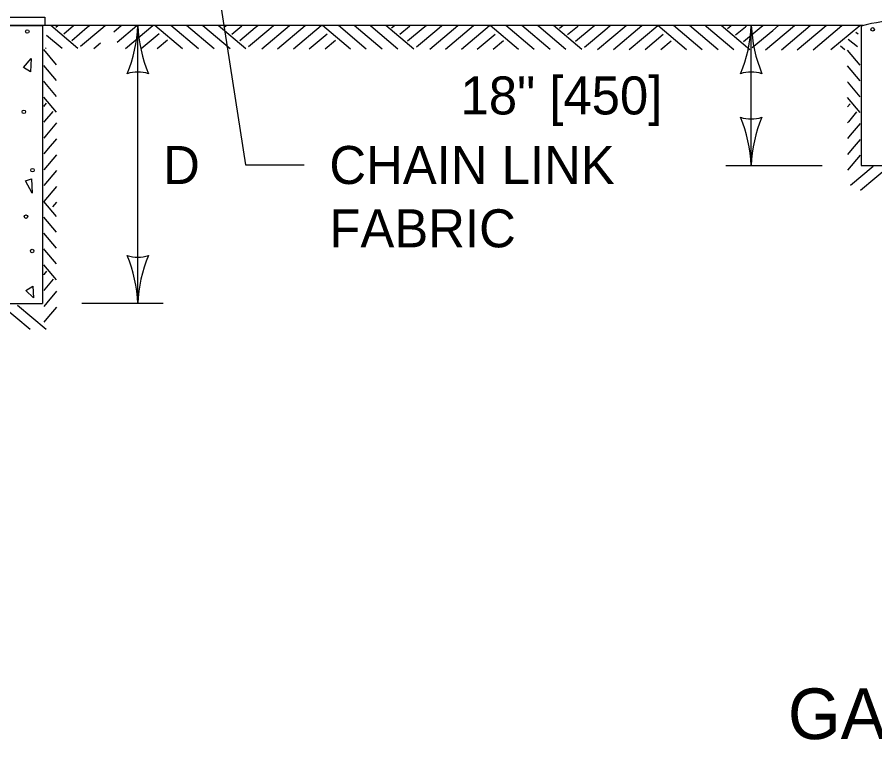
# Model space of a CAD drawing. Extents: x 49973.1 to 50021, y 49987.6 to 50015.4.
# Drawn here: x 50004.493 to 50005.847, y 49993.862 to 49995.003 of the extents above; entities that cross this region are included whole.
import ezdxf

# ---------------------------------------------------------------- set-up
doc = ezdxf.new("R2010")
doc.units = 0
for name, color, linetype in [('Level 1', 7, 'Continuous'), ('Level 2', 7, 'Continuous'), ('Level 3', 7, 'Continuous')]:
    doc.layers.add(name, color=color, linetype=linetype)

msp = doc.modelspace()

# ---------------------------------------------------------------- linework, layer by layer
at = {"layer": 'Level 1'}
for p, q in [((50004.4035, 49994.9902), (50004.5335, 49994.9902)), ((50004.5335, 49994.9902), (50004.5335, 49994.5511)), ((50005.8287, 49994.9902), (50004.5335, 49994.9902)), ((50004.5894, 49994.954), (50004.5465, 49994.9901)), ((50004.5544, 49994.9875), (50004.5575, 49994.9901)), ((50004.5671, 49994.9773), (50004.5825, 49994.9901)), ((50004.5796, 49994.9668), (50004.6042, 49994.9874)), ((50004.5935, 49994.9574), (50004.6258, 49994.9845)), ((50004.6042, 49994.9874), (50004.6075, 49994.9901)), ((50004.6258, 49994.9845), (50004.6326, 49994.9901)), ((50004.6459, 49994.9803), (50004.6576, 49994.9901)), ((50004.6515, 49994.9641), (50004.6826, 49994.9901)), ((50004.6644, 49994.954), (50004.7075, 49994.9901)), ((50004.6644, 49994.954), (50004.7075, 49994.9901)), ((50004.6894, 49994.954), (50004.7178, 49994.9778)), ((50004.7545, 49994.9535), (50004.711, 49994.9901)), ((50004.7795, 49994.9535), (50004.736, 49994.9901)), ((50004.8045, 49994.9535), (50004.761, 49994.9901)), ((50004.8295, 49994.9535), (50004.7865, 49994.9896)), ((50004.8545, 49994.9535), (50004.811, 49994.9901)), ((50004.8195, 49994.987), (50004.8232, 49994.9901)), ((50004.8322, 49994.9768), (50004.8479, 49994.9899)), ((50004.8447, 49994.9663), (50004.8693, 49994.9869)), ((50004.8586, 49994.9569), (50004.8909, 49994.984)), ((50004.8693, 49994.9869), (50004.8732, 49994.9901)), ((50004.8795, 49994.9535), (50004.9233, 49994.9901)), ((50004.8909, 49994.984), (50004.8983, 49994.9901)), ((50004.9045, 49994.9535), (50004.9483, 49994.9901)), ((50004.9295, 49994.9535), (50004.9732, 49994.9901)), ((50004.9545, 49994.9535), (50004.9829, 49994.9773)), ((50005.0196, 49994.953), (50004.9755, 49994.9901)), ((50005.0446, 49994.953), (50005.0005, 49994.9901)), ((50005.0696, 49994.953), (50005.0255, 49994.9901)), ((50005.0516, 49994.9891), (50005.0505, 49994.9901)), ((50005.0946, 49994.953), (50005.0516, 49994.9891)), ((50005.1196, 49994.953), (50005.0755, 49994.9901)), ((50005.0846, 49994.9865), (50005.0889, 49994.9901)), ((50005.0973, 49994.9763), (50005.113, 49994.9894)), ((50005.1098, 49994.9658), (50005.1344, 49994.9864)), ((50005.113, 49994.9894), (50005.1139, 49994.9901)), ((50005.1237, 49994.9564), (50005.156, 49994.9835)), ((50005.1344, 49994.9864), (50005.1389, 49994.9901)), ((50005.1446, 49994.953), (50005.189, 49994.9901)), ((50005.156, 49994.9835), (50005.164, 49994.9901)), ((50005.1696, 49994.953), (50005.214, 49994.9901)), ((50005.1946, 49994.953), (50005.2389, 49994.9901)), ((50005.2196, 49994.953), (50005.248, 49994.9768)), ((50005.2847, 49994.9525), (50005.24, 49994.9901)), ((50005.3097, 49994.9525), (50005.265, 49994.9901)), ((50005.3347, 49994.9525), (50005.29, 49994.9901)), ((50005.3167, 49994.9886), (50005.315, 49994.9901)), ((50005.3597, 49994.9525), (50005.3167, 49994.9886)), ((50005.3847, 49994.9525), (50005.34, 49994.9901)), ((50005.3497, 49994.986), (50005.3547, 49994.9902)), ((50005.3624, 49994.9758), (50005.3781, 49994.9889)), ((50005.3749, 49994.9653), (50005.3995, 49994.9859)), ((50005.3781, 49994.9889), (50005.3796, 49994.9901)), ((50005.3888, 49994.9559), (50005.4211, 49994.983)), ((50005.3995, 49994.9859), (50005.4046, 49994.9901)), ((50005.4097, 49994.9525), (50005.4547, 49994.9901)), ((50005.4211, 49994.983), (50005.4297, 49994.9901)), ((50005.4347, 49994.9525), (50005.4797, 49994.9901)), ((50005.4597, 49994.9525), (50005.5045, 49994.9901)), ((50005.5498, 49994.952), (50005.5045, 49994.9901)), ((50005.5748, 49994.952), (50005.5295, 49994.9901)), ((50005.5998, 49994.952), (50005.5545, 49994.9901)), ((50005.5818, 49994.9881), (50005.5795, 49994.9901)), ((50005.6248, 49994.952), (50005.5818, 49994.9881)), ((50005.6498, 49994.952), (50005.6045, 49994.9901)), ((50005.6148, 49994.9855), (50005.6198, 49994.9897)), ((50005.6198, 49994.9897), (50005.6203, 49994.9901)), ((50005.6275, 49994.9753), (50005.6432, 49994.9884)), ((50005.64, 49994.9648), (50005.6646, 49994.9854)), ((50005.6432, 49994.9884), (50005.6453, 49994.9901)), ((50005.6539, 49994.9554), (50005.6862, 49994.9825)), ((50005.6646, 49994.9854), (50005.6703, 49994.9901)), ((50005.6748, 49994.952), (50005.7203, 49994.9901)), ((50005.6862, 49994.9825), (50005.6954, 49994.9901)), ((50005.6998, 49994.952), (50005.7453, 49994.9901)), ((50005.7248, 49994.952), (50005.7702, 49994.9901)), ((50005.7498, 49994.952), (50005.7953, 49994.9901)), ((50005.778, 49994.9521), (50005.8235, 49994.9902)), ((50005.8209, 49994.9763), (50005.8174, 49994.9792)), ((50005.8257, 49994.9894), (50005.8257, 49994.7693)), ((50004.5644, 49994.954), (50004.5398, 49994.9746)), ((50004.7144, 49994.954), (50004.7307, 49994.9677)), ((50004.9795, 49994.9535), (50004.9958, 49994.9672)), ((50005.2446, 49994.953), (50005.2609, 49994.9667)), ((50005.4847, 49994.9525), (50005.5131, 49994.9763)), ((50005.5097, 49994.9525), (50005.526, 49994.9662)), ((50005.8197, 49994.9563), (50005.8053, 49994.9683)), ((50004.5553, 49994.9284), (50004.5354, 49994.9521)), ((50004.5394, 49994.954), (50004.5381, 49994.9551)), ((50004.6144, 49994.954), (50004.6248, 49994.9627)), ((50005.7998, 49994.952), (50005.793, 49994.9577)), ((50005.8242, 49994.9277), (50005.8043, 49994.9514)), ((50004.5553, 49994.9034), (50004.5354, 49994.9271)), ((50005.8242, 49994.9027), (50005.8043, 49994.9264)), ((50004.5369, 49994.9004), (50004.5354, 49994.9021)), ((50004.5553, 49994.8784), (50004.5369, 49994.9004)), ((50005.8058, 49994.8997), (50005.8043, 49994.9014)), ((50005.8242, 49994.8777), (50005.8058, 49994.8997)), ((50004.5553, 49994.8534), (50004.5354, 49994.8771)), ((50005.8242, 49994.8527), (50005.8043, 49994.8764)), ((50004.5395, 49994.8674), (50004.5353, 49994.8624)), ((50005.8084, 49994.8667), (50005.8042, 49994.8617)), ((50004.5497, 49994.8547), (50004.5366, 49994.839)), ((50005.8186, 49994.854), (50005.8055, 49994.8383)), ((50004.5366, 49994.839), (50004.5354, 49994.8375)), ((50004.5553, 49994.8363), (50004.5396, 49994.8176)), ((50005.8055, 49994.8383), (50005.8043, 49994.8368)), ((50005.8242, 49994.8356), (50005.8085, 49994.8169)), ((50004.5396, 49994.8176), (50004.5354, 49994.8125)), ((50005.8085, 49994.8169), (50005.8043, 49994.8118)), ((50004.5553, 49994.8112), (50004.5425, 49994.796)), ((50005.8242, 49994.8105), (50005.8114, 49994.7953)), ((50004.5425, 49994.796), (50004.5354, 49994.7874)), ((50005.8114, 49994.7953), (50005.8043, 49994.7867)), ((50004.5553, 49994.7862), (50004.5354, 49994.7624)), ((50005.8242, 49994.7855), (50005.8043, 49994.7617)), ((50004.5553, 49994.7612), (50004.5354, 49994.7374)), ((50005.8089, 49994.7384), (50005.8445, 49994.7681)), ((50005.8248, 49994.7305), (50005.8698, 49994.7681)), ((50005.8257, 49994.7693), (50005.9557, 49994.7693)), ((50004.5553, 49994.7363), (50004.5354, 49994.7126)), ((50004.5553, 49994.6889), (50004.5354, 49994.7126)), ((50004.5553, 49994.7112), (50004.5492, 49994.704)), ((50004.5553, 49994.6639), (50004.5354, 49994.6876)), ((50004.5553, 49994.6389), (50004.5354, 49994.6626)), ((50004.5374, 49994.6353), (50004.5354, 49994.6376)), ((50004.5553, 49994.6139), (50004.5374, 49994.6353)), ((50004.5553, 49994.5889), (50004.5354, 49994.6126)), ((50004.54, 49994.6023), (50004.5358, 49994.5973)), ((50004.5358, 49994.5973), (50004.5354, 49994.5968)), ((50004.5502, 49994.5896), (50004.5371, 49994.5739)), ((50004.5371, 49994.5739), (50004.5354, 49994.5718)), ((50004.5553, 49994.5706), (50004.5401, 49994.5525)), ((50004.4035, 49994.5511), (50004.5335, 49994.5511)), ((50004.5142, 49994.5101), (50004.4689, 49994.5482)), ((50004.5392, 49994.5101), (50004.4939, 49994.5482)), ((50004.5401, 49994.5525), (50004.5354, 49994.5468)), ((50004.5553, 49994.5455), (50004.543, 49994.5309)), ((50004.543, 49994.5309), (50004.5354, 49994.5217))]:
    msp.add_line(p, q, dxfattribs=at)
for points in [[(50004.4319, 49994.9902), (50004.4319, 49995.0033), (50004.5374, 49995.0033), (50004.5374, 49994.9902)], [(50004.5033, 49994.9239), (50004.5157, 49994.9383), (50004.5143, 49994.9171)], [(50004.5067, 49994.7448), (50004.5163, 49994.7483), (50004.517, 49994.7256)], [(50004.5074, 49994.5719), (50004.5184, 49994.5788), (50004.5191, 49994.5603)]]:
    msp.add_lwpolyline(points, close=True, dxfattribs=at)
for centre in [(50004.5095, 49994.9808), (50005.8439, 49994.9841), (50004.504, 49994.8539), (50004.5177, 49994.7619), (50004.5075, 49994.6885), (50004.5171, 49994.6343)]:
    msp.add_circle(centre, 0.00279, dxfattribs=at)
msp.add_arc((50005.8907, 49994.7481), 0.2499, 74.9261, 105.0737, dxfattribs=at)
at = {"layer": 'Level 3'}
for p, q in [((50004.763, 49995.3524), (50004.8541, 49994.77)), ((50004.6839, 49994.5511), (50004.6839, 49994.9902)), ((50005.6522, 49994.7693), (50005.6522, 49994.9902)), ((50004.8541, 49994.77), (50004.9463, 49994.77)), ((50005.6122, 49994.7693), (50005.7643, 49994.7693)), ((50004.7239, 49994.5511), (50004.5953, 49994.5511))]:
    msp.add_line(p, q, dxfattribs=at)
for centre, radius, start, end in [((50004.4618, 49994.9994), 0.2223, 337.456, 357.6395), ((50004.9166, 49995.0017), 0.233, 182.8273, 202.0772), ((50005.4301, 49994.9994), 0.2223, 337.456, 357.6395), ((50005.8849, 49995.0017), 0.233, 182.8273, 202.0772), ((50004.6839, 49994.862), 0.0548, 72.1388, 107.8612), ((50005.6522, 49994.862), 0.0548, 72.1388, 107.8612), ((50005.6522, 49994.8975), 0.0548, 252.1388, 287.8612), ((50005.4195, 49994.7578), 0.233, 2.8273, 22.0772), ((50005.8743, 49994.7602), 0.2223, 157.456, 177.6395), ((50004.6839, 49994.6793), 0.0548, 252.1388, 287.8612), ((50004.4512, 49994.5396), 0.233, 2.8273, 22.0772), ((50004.906, 49994.542), 0.2223, 157.456, 177.6395)]:
    msp.add_arc(centre, radius, start, end, dxfattribs=at)

# ---------------------------------------------------------------- texts
at = {"layer": 'Level 2'}
for s, height, p in [('18" [450]', 0.06, (50005.1934, 49994.8498)), ('CHAIN LINK', 0.06, (50004.9863, 49994.74)), ('D', 0.06, (50004.7239, 49994.74)), ('FABRIC', 0.06, (50004.9863, 49994.64)), ('GATES', 0.08, (50005.7101, 49993.8635))]:
    msp.add_text(s, height=height, dxfattribs=at).set_placement(p)

doc.saveas('drawing.dxf')
